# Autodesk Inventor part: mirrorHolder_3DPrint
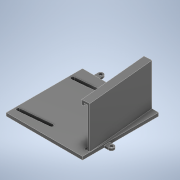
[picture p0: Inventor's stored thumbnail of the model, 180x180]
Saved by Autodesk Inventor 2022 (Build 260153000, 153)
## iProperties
Created: 2022-11
Part Number: mirrorHolder_3DPrint
Material: Generic
Document SubType Name: Modeling
Designer: Wojtus
Density: 1 g/cm^3
Appearance: Default
Author: Wojtus
Part Number: mirrorHolder
Material: Acetal Resin, Black
Density: 1.425 g/cm^3
Appearance: Smooth - Black
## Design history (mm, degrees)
sketch "Sketch1"
  geometry: L1 (-35, -35)-(35, -35); L2 (35, -35)-(35, 35); L3 (35, 35)-(-35, 35); L4 (-35, 35)-(-35, -35); L5 (-35, -35)-(35, 35); L6 (35, -35)-(-35, 35); 1 further point
  constraints: 12 end point, 2 midpoint, 2 parallel, 1 horizontal, 1 perpendicular
  dimensions: "d0" = 70 distance of L3.end L2.end; "d1" = 70 distance of L2.end L1.end
extrude "Extrusion1" new body sketch "Sketch1" distance "d2" = 3; taper "d3" = 0 deg
sketch "Sketch2"
  geometry: L1 (35, -35)-(35, 35) reference; L2 (35, -30)-(28.856, 35); L3 (21.824, 35)-(28.031, -30.659); L4 (28.031, -30.659)-(35, -30); L5 (-35, -35)-(35, -35) reference; L6 (35, 35)-(-35, 35) reference; L7 (28.856, 35)-(26.856, 35); L8 (26.856, 35)-(32.826, -28.159); L9 (32.826, -28.159)-(29.839, -28.441); L10 (29.839, -28.441)-(23.842, 35); L11 (23.842, 35)-(21.824, 35); L12 (23.842, 35)-(26.856, 35); L13 (32.826, -28.159)-(34.808, -27.971); 2 further points
  constraints: 20 end point, 5 point on line, 4 perpendicular, 1 collinear
  dimensions: "d4" = 5 distance from line of L5 L2.start; "d5" = 7 distance between parallel lines of L3 L2 (computed from d8); "d6" = 5.4 deg angle of L2 L1; "d7" = 0 distance from line of L6 L3.start; "d8" = 3 distance between parallel lines of L10 L8; "d10" = 2 distance of L2.end L7.end (= -0.5 x d8 + 0.5 x d5); "d12" = 95.4 deg angle of L6 L2 (derived); "d13" = 84.6 deg angle of L8 L6 (computed from d12); "d14" = 63.15876 vertical distance of L7.end L8.end (computed from d15); "d15" = 65.65876 vertical distance of L3.start L3.end (derived)
extrude "Extrusion3" cut sketch "Sketch2" distance "d18" = 1.5; taper "d19" = 0 deg
extrude "Extrusion5" join sketch "Sketch2" distance "d23" = 38.5; taper "d24" = 0 deg
sketch "Sketch4"
  geometry: L1 (0, 0)-(0, 40) reference; L2 (63.44, 1.5)-(63.44, 40) reference; L3 (0, 40)-(63.44, 40); L4 (63.44, 40)-(63.44, 36); L5 (63.44, 36)-(0, 36); L6 (0, 36)-(0, 40); 3 further points
  constraints: 8 end point, 2 parallel, 1 horizontal, 1 perpendicular, 1 point on line
  dimensions: "d25" = 4 distance of L3.end L4.end (= 2 x d10)
extrude "Extrusion6" join sketch "Sketch4" distance "d26" = 5 (= d8 + d10); taper "d27" = 0 deg
sketch "Sketch5"
  geometry: L1 (0, 0)-(3, 0); L2 (3, 0)-(3, 2); L3 (3, 2)-(0, 2); L4 (0, 2)-(0, 0); 1 further point
  constraints: 8 end point, 2 parallel, 1 horizontal, 1 perpendicular
  dimensions: "d28" = 3 distance of L3.end L2.end (= d8); "d29" = 2 distance of L2.end L1.end (= d10)
extrude "Extrusion7" cut sketch "Sketch5" extent not by distance; stored distance "d30" = 0; taper "d31" = 0 deg
sketch "Sketch6"
  geometry: L1 (-33.593, -27.151)-(-2.407, -24.203); L2 (27.848, -28.629)-(21.878, 34.529) reference; L3 (-31.849, -28.593)-(-3.849, -25.946); L4 (-4.151, -22.76)-(-32.151, -25.407); L5 (-35, 35)-(-35, -35) reference; L6 (-35, -35)-(35, -35) reference; L7 (-35, 35)-(-35, -35) reference; L8 (-33.593, 22.849)-(-2.407, 25.797); L9 (-31.849, 21.407)-(-3.849, 24.054); L10 (-4.151, 27.24)-(-32.151, 24.593); A1 r 1.6 centre (-32, -27) between (-32.151, -25.407) and (-31.849, -28.593); A2 r 1.6 centre (-4, -24.353) between (-3.849, -25.946) and (-4.151, -22.76); A3 r 1.6 centre (-32, 23) between (-32.151, 24.593) and (-31.849, 21.407); A4 r 1.6 centre (-4, 25.647) between (-3.849, 24.054) and (-4.151, 27.24); 3 further points
  constraints: 16 end point, 12 point on circle, 8 tangent, 4 centre point, 4 point on line, 2 midpoint, 2 parallel, 1 perpendicular
  dimensions: "d32" = 3.2 diameter of A2; "d33" = 3 distance from line of L5 A1.centre; "d34" = 8 distance from line of L6 A1.centre; "d41" = 28 horizontal distance of L4.start L4.end; "d43" = 3.2 diameter of A4; "d44" = 3 distance from line of L5 A3.centre; "d45" = 28 horizontal distance of L9.start L9.end; "d46" = 90 deg angle of L2 L9; "d47" = 50 distance of A1.centre A3.centre
extrude "Extrusion8" cut sketch "Sketch6" extent not by distance; stored distance "d48" = 0; taper "d49" = 0 deg
sketch "Sketch7" dims "d55" = 5
  geometry: L1 (35, 35)-(35, -35) reference; L2 (35, 10)-(39.102, 10); L3 (39.102, 10)-(39.102, 15); L4 (39.102, 15)-(35, 15); L5 (35, 15)-(35, 10); L6 (35, -35)-(-35, -35) reference; L7 (23.842, -35)-(-35, -35) reference; L8 (-25.574, -35)-(-20.574, -35); L9 (-20.574, -35)-(-20.574, -39.711); L10 (-20.574, -39.711)-(-25.574, -39.711); L11 (-25.574, -39.711)-(-25.574, -35); C1 r 1.6 at (39.102, 12.5); C2 r 1.6 at (-23.074, -39.711); 9 further points
  constraints: 16 end point, 4 parallel, 2 centre point, 2 coincident, 2 horizontal, 2 midpoint, 2 perpendicular, 2 point on line, 6 other
  dimensions: "d50" = 3.2 diameter of C1; "d52" = 50 distance of L4.end L1.end; "d54" = 45 distance between parallel lines of L6 L2; "d56" = 3.2 diameter of C2
extrude "Extrusion9" join sketch "Sketch7" distance "d57" = 2; taper "d58" = 0 deg
body "Solid1"
